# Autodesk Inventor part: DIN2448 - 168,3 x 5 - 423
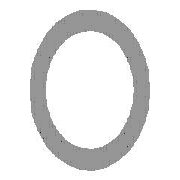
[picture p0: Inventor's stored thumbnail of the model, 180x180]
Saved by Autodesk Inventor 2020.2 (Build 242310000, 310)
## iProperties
Created: 2019-01
Part Number: DIN2448 - 168,3 x 5 - 423
Material: Acier, doux
Description: Tube
Document SubType Name: Modeling
Standard: DIN
Designer: t.sancier
Standards Organization: DIN
Language: fr-FR
Size Designation: 168,3 x 5
Categories: <MemberInstance><Categories><Category DisplayName="Profilés" InternalName="089c4875-fa83-4c05-b084-43b9cc11f5ed" Mnemonic="GRDR"><CategoryParameter DisplayName=
Stock Number: 168,3 x 5
Density: 7.85 g/cm^3
Appearance: Vert turquoise
_CCFamilyMember: 179
_CCFamilyDisplayName: DIN 2448 - Tube — DIN 2448 retirée et remplacée par DIN EN 10220
_FrameMemberDoc: Frame Member File
_Version: 15.0.0
_GetPNFromCC: 1
G_L: 423,000 mm
G_W: 168,300 mm
G_H: 168,300 mm
IsCustomPart: 1
Author: t.sancier
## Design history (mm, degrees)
node "Plan de départ"
node "Plan de fin"
sketch "Esquisse"
  geometry: C1 r 79.15 at (0, 0); C2 r 84.15 at (0, 0); 2 further points
  constraints: 3 coincident, 2 centre point
  dimensions: "d0" = 168.3 diameter of C2 (= G_H); "d1" = 5 radial gap between concentric circles of C2 C1 (= G_T)
extrude "Corps" new body sketch "Esquisse" stored distance "d2" = 423 (= G_L); taper "d3" = 0 deg
node "Driven Length"
  sketch "Sketch3"
    geometry: L1 (0, 0)-(10, 0) reference
    constraints: 2 end point, 1 horizontal
  workplane "Work Plane3"
  sketch "Sketch4"
    geometry: L1 (-2, 77)-(12, 77) reference; L2 (-2, 500)-(12, 500) reference
    dimensions: "d7" = 423 distance between parallel lines of L1 L2 (derived)
node "Plan de construction4"
sketch "Esquisse5"
  geometry: C1 r 796 at (-163.83, -114.715); A1 r 796 centre (-163.83, -114.715) between (108.418, 633.28) and (114.935, 630.876) reference; 3 further points
  constraints: 1 centre point, 1 coincident, 1 concentric
extrude "Extrusion2" cut sketch "Esquisse5" stored distance "d8" = 300; taper "d9" = 0 deg
body "Solid1"
node "Référence1"
other parameters: "G_H" = 168.3 [user parameter; used in 1 equation term], "G_T" = 5 [user parameter; used in 1 equation term], "G_L" = 423 (= d7) [user parameter; used in 1 equation term], "G_OFFSET_START" = -77 [user parameter; used in 1 equation term], "d4" = 77 (= -G_OFFSET_START), "d6" = 90 deg
